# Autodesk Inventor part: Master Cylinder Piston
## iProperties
Shininess: 100.0
Angle Display Precision: 2
Document Length Units: 11269
Document Angle Units: 11279
Document Time Units: 11290
Document Mass Units: 11283
Document Length Units Precision: 3
Document Angle Units Precision: 2
Compacted: True
Created: 2001-08
Part Number: Master Cylinder Piston
Document SubType Name: Modeling
Designer: Martin Budgell
Density: 0.0
Volumn: 0.0
Area: 0.0
PropertySet Name: Model Information
Control State: 0
Master: False
Checked Out: False
Author: Martin Budgell
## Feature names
1. Extrusion1
2. Revolution1
3. Chamfer1
4. Fillet1
5. Extrusion2
6. Fillet2
